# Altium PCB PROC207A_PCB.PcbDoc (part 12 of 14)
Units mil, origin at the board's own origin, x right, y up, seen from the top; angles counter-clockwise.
Board outline 4094.49 x 3724.79 mil, 8 copper layers (Top Layer, L2_GND1, L3_SIG1, L4_PWR1, L5_PWR2, L6_SIG2, L7_GND2, Bottom Layer), stack 58.1 mil thick; 584 components, 399 nets, 8440 pads, 5258 vias.
Unrouted connection lines stored in the file: 9.
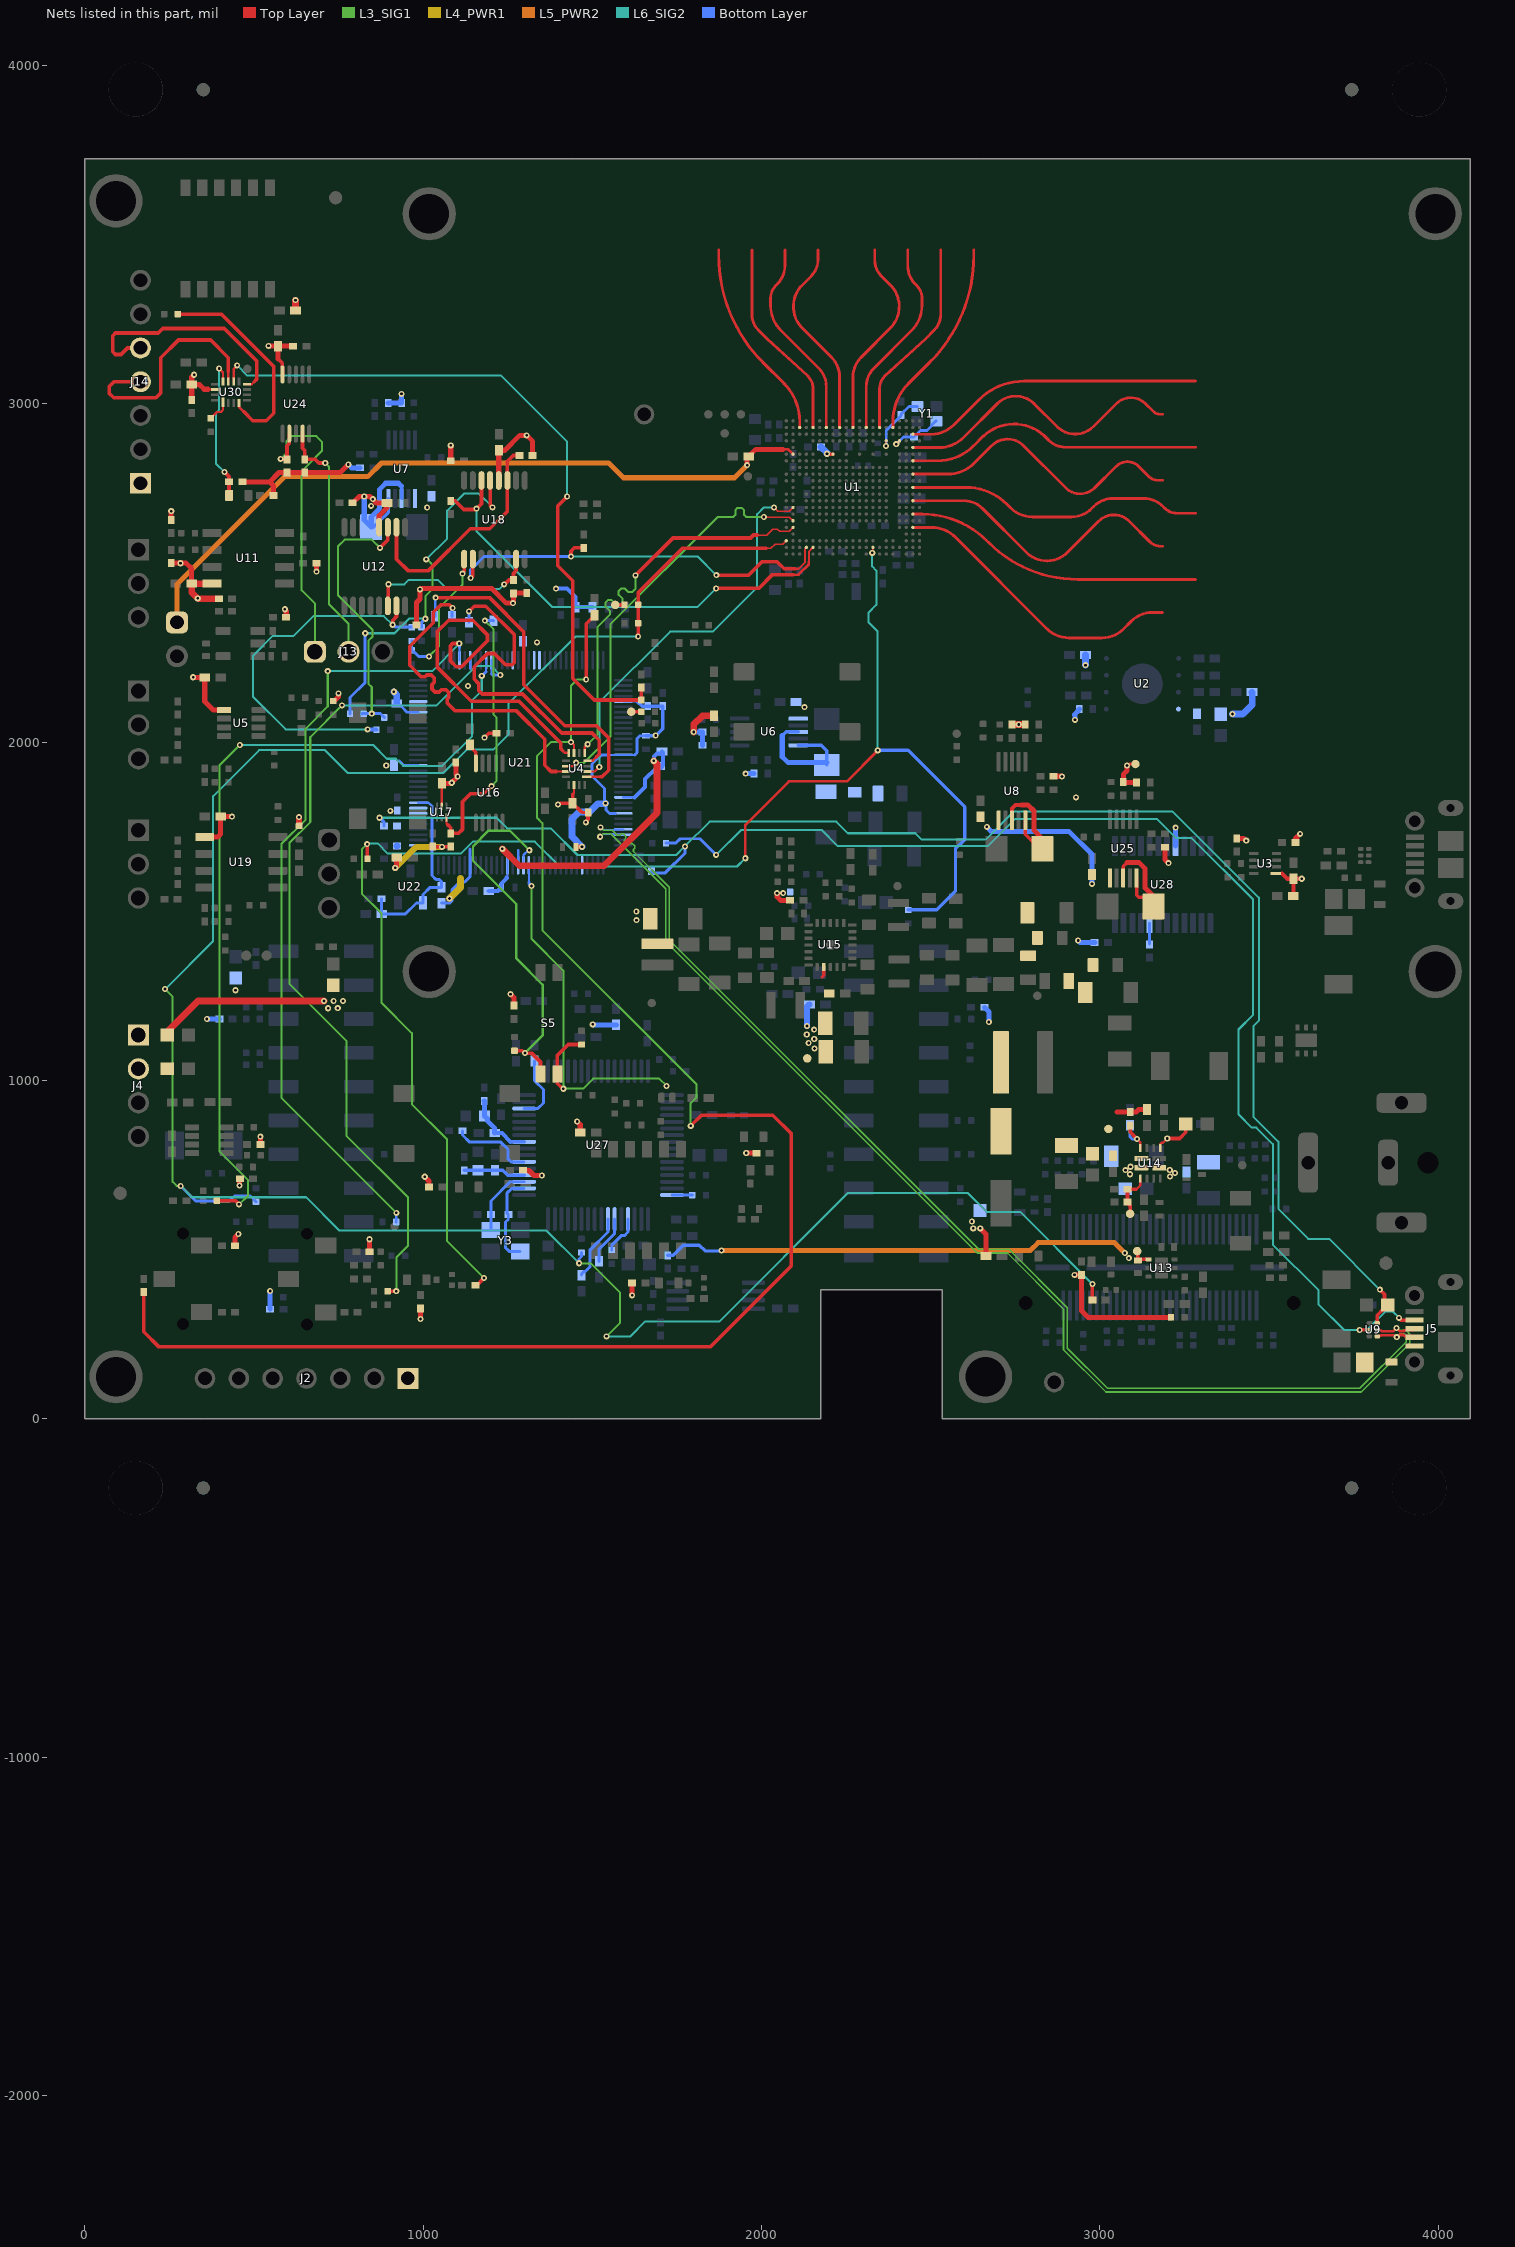
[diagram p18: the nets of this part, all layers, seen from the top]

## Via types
v1: diameter 13.77, hole 7, Top Layer to L2_GND1, tented top, 4306 vias
v2: diameter 18, hole 8, Top Layer to Bottom Layer, tented both sides, 946 vias
v3: diameter 19.68, hole 8, Top Layer to Bottom Layer, tented both sides, 6 vias

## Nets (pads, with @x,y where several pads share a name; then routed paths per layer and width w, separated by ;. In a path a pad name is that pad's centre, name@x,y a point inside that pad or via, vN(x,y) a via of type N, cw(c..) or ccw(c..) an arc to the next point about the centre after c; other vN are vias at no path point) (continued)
RADAR_USER_LED_GPIO_6: R222.1 R242.2 R263.2 R264.2 R269.2 U1.AA19 | length 7063.8
  Top Layer w4: 2014.31,2573.02 2027.72,2573.02 2040.47,2585.77 2063.47,2585.77 U1.AA19@2073.47,2595.77
  Top Layer w10.8: v2(1635.26,2312.74) R264.2@1635.26,2351.95 R269.2@1635.26,2406.15 1635.26,2442.97 1765.31,2573.02 2014.31,2573.02 ; R263.2@2977.86,351.35 2977.86,398.33 v2(2978.22,398.69)
  L3_SIG1 w6: v2(236.88,1270.33) 259.2,1248.05 259.2,700.51 271.18,688.54 v2(283.06,688.54) ; v2(1460.84,459.82) 1495.18,459.82 1582,373 1582,284 v2(1542,244)
  L6_SIG2 w6: v2(236.88,1270.33) 379.16,1412.61 379.16,1840.8 515.17,1976.8 709.66,1976.8 777.32,1909.14 1059.03,1909.14 1128.08,1978.2 1206.97,1978.2 1251.54,2022.76 1251.54,2113.54 1450.73,2312.74 v2(1635.26,2312.74) ; v2(283.06,688.54) 316.53,655.07 653.73,655.07 751.97,556.83 1363.83,556.83 v2(1460.84,459.82) ; v2(1542,244) 1612.79,244 1656.79,288 1876.04,288 2255.52,667.48 2609.94,667.48 2665.65,611.77 2765.14,611.77 v2(2978.22,398.69)
  Bottom Layer w8.7: v2(283.06,688.54) 327.1,644.49 428.14,644.49 441.99,658.35 489.12,658.35 R222.1@505.82,641.64 ; v2(1460.84,459.82) 1460.84,472.55 1467.83,479.54 R242.2@1467.83,491.55
RADAR_USER_SW_GPIO_2: R66.2 R175.1 R214.2 U1.H20 | length 4660.7
  Top Layer w4: v2(2327.26,2559.93) 2329.38,2562.05 U1.H20@2329.38,2576.08
  Top Layer w8: v2(1952.11,1657.11) 1952.11,1756.07 2080.64,1884.6 2252.16,1884.6 v2(2343.54,1975.99)
  Top Layer w10.8: R214.2@834.13,1655.53 v2(834.13,1698.84) ; R66.2@1154.24,394.98 1158.82,394.98 v2(1179.95,416.12)
  L3_SIG1 w6: v2(834.13,1698.84) 818.86,1683.58 818.86,1552.45 876.76,1494.56 876.76,1229.96 966.37,1140.35 966.37,930.45 1070.96,825.86 1070.96,525.12 v2(1179.95,416.12)
  L6_SIG2 w6: v2(834.13,1698.84) 836.42,1701.14 865.15,1701.14 895.35,1670.93 1111.38,1670.93 1146.6,1706.15 1330.25,1706.15 1403.74,1632.66 1927.66,1632.66 v2(1952.11,1657.11) ; v2(2327.26,2559.93) 2326.77,2559.45 2326.77,2520.23 2339.51,2507.49 2339.51,2405.95 2316.34,2382.78 2316.34,2354.72 2343.54,2327.51 v2(2343.54,1975.99)
  Bottom Layer w10: v2(2343.54,1975.99) 2433.17,1975.99 2600.45,1808.71 2600.45,1712.33 2573.35,1685.23 2573.35,1559.47 2518.24,1504.36 R175.1@2433.97,1504.36
RADAR_VBGAP: C6.1 U1.P6 | length 45.6
  Top Layer w10: v2(2193.39,2852.89) 2194.61,2851.67 U1.P6@2211.27,2851.67
  Bottom Layer w20: C6.1@2176.2,2873.02 2193.39,2855.83 v2(2193.39,2852.89)
REF_FTDI: R218.2 U27.6 | length 243.9
  Bottom Layer w8.7: R218.2@1116.06,851.44 1116.06,839.23 1137.51,817.77 1229.48,817.77 1250.51,796.74 1250.51,768.55 1259.21,759.84 U27.6@1298.34,759.84
REG_1V2: C20.2 C91.2 FB2.2 R193.1 U8.8 U8.10 | length 337.2
  Top Layer w11: U8.10@2779.84,1769.27 2779.84,1727.89 R193.1@2823.58,1684.15
  Top Layer w12: U8.8@2740.47,1769.27 2740.47,1804.47 2751,1815 2768.93,1815
  Top Layer w15: 2768.93,1815 2786.86,1815 2805.37,1796.49 2805.37,1739.68 2830.27,1714.78 R193.1@2830.27,1684.93
REG_1V8: C3.2 C82.2 FB1.2 R192.1 U6.8 U6.10 | length 385.1
  Bottom Layer w10: 2061.32,2019.32 2072.7,2030.71 U6.8@2108.47,2030.71 ; U6.10@2108.66,1991.15 2176.34,1991.15 2193,1974.49 R192.1@2193,1933.08
  Bottom Layer w15: 2061.32,2019.32 2061.32,1957.23 2077.83,1940.72 R192.1@2193,1940.72
REG_RF_1V2: C27.2 C103.2 FB3.2 R134.1 U25.8 U25.10 | length 351
  Top Layer w10: U25.8@3069.32,1599.03 3069.32,1632.87 3080.56,1644.11 ; U25.10@3108.69,1599.03 3108.69,1548.23 3114.55,1542.37 3136.94,1542.37 3159.12,1520.2 R134.1@3159.12,1514.68
  Top Layer w15: 3080.56,1644.11 3116.35,1644.11 3134.22,1626.24 3134.22,1569.44 3159.12,1544.54 R134.1@3159.12,1514.68
RS232_FTDI_RX: R120.1 U27.48 | length 60
  Bottom Layer w8.7: U27.48@1735.35,661.42 R120.1@1795.35,661.42
RS232_FTDI_TX: R121.1 U27.52 | length 117.2
  Bottom Layer w8.7: R121.1@1557.21,498.88 1557.21,513.45 1585.08,541.32 1594.62,541.32 1605.43,552.13 U27.52@1605.43,590.55
RST_FTDI: R237.2 U27.14 | length 198.4
  Bottom Layer w8.7: U27.14@1298.34,917.33 1338.8,917.33 1355.24,933.76 1355.24,973.27 1328.96,999.54 R237.2@1328.96,1057.6
RTC_CLK_IN: R269.1 TP9.1 | length 27.4
  Top Layer w10.8: TP9.1@1567.54,2405.99 1594.74,2405.99 R269.1@1594.9,2406.15
RX1: U1.W2 | length 597.4
  Top Layer w8.39: 1873.81,3437.36 ccw(c2317.7,3437.36) 2003.77,3123.54 ; 1873.81,3437.4 1873.81,3455.15 ; 2003.87,3123.44 2065.97,3061.34 ; 2066.02,3061.29 cw(c1953.11,2948.31) 2112.84,2948.36 ; U1.W2@2112.84,2930.41 2112.84,2948.28
RX2: U1.U2 | length 597.6
  Top Layer w8.39: 1971.45,3455.15 1971.45,3265.17 ccw(c2038.05,3265.13) 1990.93,3218.07 ; 1990.99,3218.01 2017,3192 2137.05,3082.32 cw(c2099.92,3045.5) 2152.21,3045.5 U1.U2@2152.21,2930.41
RX3: U1.R2 | length 597
  Top Layer w8.39: 2069.09,3455.15 2069.09,3408.26 cw(c1993.02,3408.26) 2046.81,3354.47 2042.21,3349.87 ccw(c2079.28,3312.81) 2026.86,3312.81 2026.86,3291.54 ccw(c2132.46,3291.54) 2057.79,3216.87 2169.65,3105.01 ; 2169.75,3104.91 cw(c2116.91,3052.15) 2191.58,3052.15 ; U1.R2@2191.58,2930.41 2191.58,3052.11
RX4: U1.N2 | length 597.1
  Top Layer w8.39: 2166.73,3455.15 2166.73,3425.44 cw(c2100.71,3425.44) 2147.33,3378.69 2116.33,3347.7 ccw(c2185.48,3288.13) 2117.64,3227.07 2206.65,3138.06 ; 2206.74,3137.97 cw(c2148.13,3079.46) 2230.95,3079.49 ; U1.N2@2230.95,2930.41 2230.95,3079.42
RX5: U1.L2 | length 597.1
  Top Layer w8.39: U1.L2@2270.32,2930.41 2270.32,3079.42 ; 2270.32,3079.49 cw(c2353.14,3079.46) 2294.53,3137.97 ; 2294.62,3138.06 2383.63,3227.07 ccw(c2315.79,3288.13) 2384.94,3347.7 2353.94,3378.69 cw(c2400.56,3425.44) 2334.54,3425.44 2334.54,3455.15
RX6: U1.J2 | length 597
  Top Layer w8.39: U1.J2@2309.69,2930.41 2309.69,3052.11 ; 2309.69,3052.15 cw(c2384.36,3052.15) 2331.52,3104.91 ; 2331.62,3105.01 2443.48,3216.87 ccw(c2368.81,3291.54) 2474.41,3291.54 2474.41,3312.81 ccw(c2421.99,3312.81) 2459.06,3349.87 2454.46,3354.47 cw(c2508.25,3408.26) 2432.18,3408.26 2432.18,3455.15
RX7: U1.G2 | length 597.6
  Top Layer w8.39: U1.G2@2349.06,2930.41 2349.06,3045.5 cw(c2401.35,3045.5) 2364.22,3082.32 2484.27,3192 2510.28,3218.01 ; 2510.34,3218.07 ccw(c2463.22,3265.13) 2529.82,3265.13 2529.82,3455.15
RX8: U1.E2 | length 597.4
  Top Layer w8.39: U1.E2@2388.43,2930.41 2388.43,2948.28 ; 2388.43,2948.36 cw(c2548.16,2948.31) 2435.25,3061.29 ; 2435.3,3061.34 2497.4,3123.44 ; 2497.5,3123.54 ccw(c2183.57,3437.36) 2627.46,3437.36 ; 2627.46,3437.4 2627.46,3455.15
SOP0_FTDI: R249.1 U27.55 | length 200.5
  Bottom Layer w8.7: R249.1@1468.31,424.73 1468.31,428.66 1475.77,436.12 1479.7,436.12 1492.39,448.81 1492.39,498.39 1546.38,552.38 U27.55@1546.38,590.55
SOP1_FTDI: R248.1 U27.54 | length 144.6
  Bottom Layer w8.7: R248.1@1519.16,465.41 1519.16,500.71 1566.06,547.61 U27.54@1566.06,590.55
SPI_MUX_ENn: R10.1 U28.20 | length 61.9
  Bottom Layer w8.7: R10.1@3147.41,1403.19 U28.20@3147.41,1465.05
SPIB_CLK: R285.2 U30.1 | length 69.6
  Top Layer w7: R285.2@371.87,2957.78 372.36,2957.78 378.21,2963.63 378.21,2964.13 390.46,2976.38 401.91,2976.38 408.24,2982.71 U30.1@408.24,3005.31
SPIB_CS0_N: J14.4 U30.11 | length 700.7
  Top Layer w7: U30.11@423.99,3066.34 423.99,3094.85
  Top Layer w10.8: J14.4@164.17,3065.75 86.01,3065.75 71.97,3051.7 71.97,3030.95 84.85,3018.06 209.81,3018.06 224.17,3032.43 224.17,3136.95 276.57,3189.36 371.67,3189.36 423.99,3137.04 423.99,3094.85
SPIB_MISO: J14.5 U30.8 | length 703.8
  Top Layer w7: U30.8@479.11,3058.46 493.33,3058.46 500.4,3065.53
  Top Layer w10.8: J14.5@164.17,3165.75 163.82,3165.39 125.78,3165.39 106.76,3146.38 90.06,3146.38 82.21,3154.23 82.21,3201.74 90.12,3209.66 216.36,3209.66 230.05,3223.35 411.61,3223.35 507.46,3127.5 507.46,3072.6 500.4,3065.53
SPIB_MOSI: R286.2 U30.4 | length 626.5
  Top Layer w7: U30.4@455.49,3003.35 455.49,2991.32 470.11,2976.69
  Top Layer w10.8: R286.2@274.53,3265.75 403.23,3265.75 558.07,3110.9 558.07,2972.72 535.9,2950.55 496.26,2950.55 470.11,2976.69
SYS_RST_OUT: D9.1 R65.2 U30.12 | length 438.3
  Top Layer w7: v2(396.6,3104.72) 408.24,3093.09 U30.12@408.24,3066.34
  Top Layer w10.8: v2(412.68,2798.7) 426.03,2785.35 R65.2@426.03,2769.64 D9.1@426.03,2729.64
  L6_SIG2 w6: v2(396.6,3104.72) 396.6,2982.52 387.21,2973.12 387.21,2824.17 v2(412.68,2798.7)
SYS_RST_OUT_SPIB_CS0_N: R146.1 R268.2 U30.10 | length 2116.5
  Top Layer w7: U30.10@439.74,3066.34 439.74,3103.81 v2(450.04,3114.12)
  Top Layer w10.8: v2(1425.36,2726.55) 1397.29,2698.47 1397.29,2521.89 1441.98,2477.2 1441.98,2188.81 1505.76,2125.04 R268.2@1644.95,2125.04 1644.95,2160.46 R146.1@1645.54,2161.05
  L6_SIG2 w6: v2(450.04,3114.12) 480.15,3084.02 1230.23,3084.02 1425.36,2888.89 v2(1425.36,2726.55)
TX1: U1.B3 | length 888.6
  Top Layer w8.39: U1.B3@2447.49,2910.73 2501.91,2910.73 ccw(c2502.08,3004.03) 2568.14,2938.14 2642.08,3012.08 cw(c2775.58,2878.79) 2775.62,3067.44 3283.26,3067.44
TX2: U1.B5 | length 888
  Top Layer w8.39: U1.B5@2447.49,2871.36 2525.95,2871.36 ccw(c2525.95,2971.36) 2596.66,2900.65 2696.89,3000.88 cw(c2751.29,2945.75) 2806.17,3000.39 ; 2806.34,3000.21 2873.54,2933.02 ccw(c2927.11,2987) 2981,2933.34 3046.18,2998.52 cw(c3091.8,2956.43) 3133.89,3002.05 3158.34,2977.6 ccw(c3177.16,2996.42) 3177.16,2969.8 3185.62,2969.8
TX3: U1.B7 | length 888.6
  Top Layer w8.39: U1.B7@2447.17,2832.19 2520.66,2832.19 ccw(c2520.75,2982.28) 2626.97,2876.24 2655.65,2904.92 cw(c2746.3,2808.18) 2843.04,2898.82 2848.98,2892.89 ccw(c2899.01,2942.92) 2899.01,2872.16 3283.26,2872.16
TX4: U1.B9 | length 888.6
  Top Layer w8.39: U1.B9@2447.49,2792.62 2551,2792.62 ccw(c2551.05,2901.87) 2628.43,2824.74 2679.29,2875.6 cw(c2727.43,2829.44) 2773.59,2877.59 2896.85,2754.33 ccw(c2942.03,2795.96) 2983.66,2750.79 3049.08,2816.2 cw(c3081.8,2782.6) 3115.03,2815.7 ; 3115.16,2815.56 3146.34,2784.38 ; 3146.39,2784.33 ccw(c3170.07,2808.02) 3170.07,2774.53 ; 3170.11,2774.53 3185.62,2774.53
TX5: U1.B11 | length 888.4
  Top Layer w8.39: U1.B11@2447.49,2753.25 2605.6,2753.25 cw(c2605.6,2583.89) 2725.4,2703.6 2735.49,2693.51 ccw(c2801.21,2759.24) 2801.21,2666.29 2916.71,2666.29 ccw(c2916.71,2749.76) 2975.74,2690.74 2982,2697 cw(c3039.85,2639.15) 3039.85,2720.96 3127.76,2720.96 cw(c3127.76,2635.62) 3188.71,2695.36 3192.11,2691.95 ccw(c3228.48,2728.32) 3228.48,2676.89 3283.26,2676.89
TX6: U1.B13 | length 888.1
  Top Layer w8.39: U1.B13@2447.49,2713.88 2599.37,2713.88 cw(c2599.34,2639.03) 2652.24,2691.98 ; 2652.31,2691.91 2784.77,2559.45 ; 2784.81,2559.41 ccw(c2790.7,2565.38) 2784.96,2559.27 ccw(c2843.79,2622.59) 2904.99,2561.55 2996.61,2653.18 ; 2996.74,2653.31 cw(c3041.99,2608.56) 3086.59,2653.97 ; 3086.62,2653.94 3147.73,2592.83 ccw(c3180.51,2625.61) 3180.51,2579.25 3185.62,2579.25
TX7: U1.B15 | length 887.8
  Top Layer w8.39: U1.B15@2447.49,2674.51 2475.12,2674.51 cw(c2475.23,2403.67) 2666.75,2595.17 ; 2666.83,2595.09 2671.77,2590.15 ccw(c2933.72,2851.99) 2933.73,2481.61 ; 2933.85,2481.61 3283.26,2481.61
TX8: U1.B17 | length 888.3
  Top Layer w8.39: U1.B17@2447.49,2635.14 2502.16,2635.14 cw(c2502.13,2533.26) 2574.19,2605.27 2844.15,2335.32 ; 2844.22,2335.24 ccw(c2908.37,2399.43) 2908.37,2308.68 ; 2908.41,2308.68 3006.7,2308.68 ; 3006.76,2308.68 ccw(c3006.76,2398.36) 3070.2,2334.97 3092.8,2357.58 cw(c3156.4,2294.15) 3156.4,2383.97 3185.62,2383.97
UARTB_RX: J13.2 R275.1 U24.4 | length 729.6
  Top Layer w10.8: U24.4@643.35,2912.24 643.35,2868.98 649.99,2862.34 R275.1@649.99,2836.81 ; R275.1@650.21,2836.59 679.9,2836.59 690.9,2825.59 v2(710.5,2825.59)
  L3_SIG1 w6: v2(710.5,2825.59) 721.39,2814.69 721.39,2407.64 779.43,2349.6 J13.2@779.43,2267.59
UARTB_TX: J13.1 R274.1 U24.2 | length 937.7
  Top Layer w10.8: v2(578.51,2837.87) 579.16,2837.23 594.55,2837.23 R274.1@597.17,2834.62 ; R274.1@597.17,2836.59 597.17,2876.67 604.01,2883.5 U24.2@604.01,2912.26
  L3_SIG1 w6: v2(578.51,2837.87) 595.34,2854.7 595.34,2889.02 611.13,2904.81 683.9,2904.81 701.46,2887.26 701.46,2862.43 640.38,2801.36 640.38,2449.39 679.43,2410.33 J13.1@679.43,2267.59
USB_5V: C86.2 J5.1 L9.1
VBAT: J4.2 R32.1
VBUS_1_DETECT: C118.2 R236.1 R239.2 U21.1 | length 2.4
  Bottom Layer w8.7: C118.2@922.79,1693.47 C118.2@924.55,1695.23
VCC_3V3: C34.1 C35.2 C36.1 C38.2 C40.1 C41.1 C52.2 C56.1 C57.1 C58.1 C59.1 C65.1 C104.1 C107.1 C109.2 C133.1 C135.1 C136.1 J2.1 J14.1 L14.2 R2.2 R5.2 R7.2 R8.2 R12.1 R14.2 R17.2 R22.2 R28.2 R44.2 R49.2 R50.1 R64.2 R65.1 R70.2 R82.2 R91.2 R94.1 R95.2 R97.2 R98.2 R99.2 R104.2 R105.2 R106.2 R107.2 R112.1 R115.1 R123.2 R127.2 R128.2 R135.2 R136.2 R138.2 R141.2 R142.1 R147.1 R149.1 R151.1 R154.2 R156.2 R157.2 R161.2 R163.2 R164.2 R165.2 R166.2 R172.2 R173.2 R200.1 R204.2 R207.2 R213.2 R253.2 R258.2 R262.2 R271.2 R274.2 R275.2 R277.2 R279.2 R283.1 R287.2 TP17.1 U2.8 U3.1 U4.14 U5.5 U6.6 U7.6 U7.8 U7.10 U8.6 U11.8 U12.12 U16.10 U17.5 U18.12 U19.5 U24.10 U25.6 U28.8 U30.14 | length 5985.8
  Top Layer w6.5: U17.5@1054.8,1809.55 1054.8,1826.78
  Top Layer w7: 362.97,3042.72 U30.14@384.62,3042.72 ; 1441.72,1845.84 1445.71,1849.83 U4.14@1445.71,1873.86
  Top Layer w8: 1054.8,1826.78 C52.2@1054.8,1878.55
  Top Layer w10: 570.67,3133.69 583.17,3121.18 583.17,3109.77 584.32,3108.62 U24.10@584.32,3087.46 ; R123.2@1028.35,1691.39 R138.2@1081.26,1691.39 ; C104.1@1137.8,1993.11 1144.61,1986.3 1144.61,1981.18 1155.59,1970.19 U16.10@1155.59,1937.85 ; v2(1181.1,2013.78) 1193.57,2026.25 R95.2@1217.06,2026.25 ; v2@1404.35,1820.02 C40.1@1441.72,1820.02 ; 1441.72,1845.84 C40.1@1441.72,1820.02 ; R5.2@1487.66,1792.41 1469.33,1792.41 C40.1@1441.72,1820.02 ; v2(3080.24,1931.12) 3082.41,1931.12 3086.94,1935.65 TP17.1@3105.44,1935.65 ; U3.1@3520.39,1611.98 3538.8,1611.98
  Top Layer w12: v2(1480.6,1763.15) 1480.6,1765.3 1487.66,1772.35 R5.2@1487.66,1792.41 ; 3538.8,1611.98 3554.27,1596.5 C36.1@3572.12,1596.5 ; C56.1@3572.22,1545.8 3572.12,1545.9 C36.1@3572.12,1596.5 ; v2(3596.96,1596.5) C36.1@3572.12,1596.5
  Top Layer w15: R97.2@254.77,2529.42 v2@282.35,2529.42 ; R98.2@254.77,2657.7 254.77,2682.89 v2(255.07,2683.18) ; v2(282.56,2529.21) v2@282.35,2529.42 ; C65.1@315.62,2468.79 315.42,2468.99 315.42,2513.32 299.32,2529.42 v2@282.35,2529.42 ; R271.2@315.66,3012.1 C136.1@315.66,3057.1 ; v2(319.74,2192.12) 319.88,2191.99 354.05,2191.99 C38.2@354.18,2191.85 354.18,2120.48 379.42,2095.24 U5.5@411.27,2095.24 ; v2(322.86,3086.49) 315.66,3079.29 C136.1@315.66,3057.1 ; U19.5@354.01,1720.14 392.47,1720.14 401.26,1728.93 C109.2@401.26,1780.14 434.36,1780.14 v2(434.5,1780) ; 362.97,3043.47 352.32,3043.47 338.69,3057.1 C136.1@315.66,3057.1 ; R204.2@443.81,512.08 443.81,536.55 v2(453.56,546.3) ; v2(457.16,689.73) 457.42,689.99 457.42,709.08 R22.2@457.67,709.34 ; R65.1@465.4,2769.64 546.41,2769.64 ; R17.2@518.5,810.73 518.5,834.19 v2(518.57,834.26) ; v2(542.61,3171.73) 542.97,3171.37 570.31,3171.37 C135.1@570.67,3171.01 ; R64.2@557.48,2729.64 557.48,2758.57 546.41,2769.64 ; 570.67,3133.69 C135.1@570.67,3171.01 ; v2(591.03,2393.29) 591.03,2392.48 595.04,2388.47 R82.2@595.04,2369.21 ; R253.2@615.67,3171.01 C135.1@570.67,3171.01 ; R161.2@684.56,2528.79 684.68,2528.66 684.68,2504.36 v2(684.8,2504.24) ; v2(778.64,2821.3) 754.55,2797.22 R275.2@650.21,2797.22 R274.2@597.17,2797.22 573.98,2797.22 546.41,2769.64 ; R7.2@791.59,2707.74 810.53,2726.68 v2(825.71,2726.68) 842.92,2726.68 851.01,2718.59 v2(851.1,2718.59) 862.11,2707.58 C41.1@892.99,2707.58 892.99,2693.18 869.69,2669.88 U12.12@869.69,2635.52 ; v2(841.23,530.81) 841.49,530.55 R207.2@841.49,494.32 ; v2(917.32,1628.63) 917.32,1629.44 921.46,1633.58 R213.2@921.46,1658.85 ; R8.2@979.95,2346.78 979.95,2413.12 990.66,2423.83 v2(990.66,2452.12) ; v2@990.09,2452.69 v2(990.66,2452.12) ; R28.2@991.94,326.81 992,326.75 992,295 v2(992.06,294.94) ; v2(1004.56,715.51) 1016.85,703.21 1016.85,687.73 1016.93,687.66 R287.2@1016.93,685.39 ; C52.2@1054.8,1878.55 1081.85,1878.55 1083.55,1880.24 v2(1084.36,1880.24) 1084.36,1880.93 1101.79,1898.36 v2(1101.79,1899.05) 1101.79,1899.86 1096.4,1905.26 R163.2@1096.4,1939.9 ; R127.2@1081.36,2832.49 1081.36,2877.7 v2(1081.41,2877.75) ; U18.12@1223.27,2773.84 1223.27,2863.03 C107.1@1223.43,2863.19 1241.5,2863.19 1285.66,2907.34 v2(1305.73,2907.34) 1323.43,2889.64 R149.1@1323.43,2847.79 ; v2(1257.75,1255.36) 1268.16,1244.95 R164.2@1268.16,1221.22 ; v2(1265.58,2411.26) 1245.7,2411.26 1202.51,2454.45 993.8,2454.45 991.47,2452.12 v2(990.66,2452.12) ; v2@1266.79,2413.33 1266.79,2440.45 1267.35,2441.03 R128.2@1306.31,2441.03 ; R165.2@1295.39,734.37 1312.74,734.37 1327.59,719.53 v2(1350.76,719.53) ; v2(1454.94,878.85) 1464.27,869.51 R70.2@1464.27,846.87 ; v2@1617.56,365.21 R141.2@1617.54,401.58 ; v2(1954.92,785.85) 1969.75,785.85 1970.37,785.23 R172.2@1984.68,785.23 ; v2@2046,1548.91 2046.58,1548.34 2046.58,1543 2057.17,1532.41 2070.84,1532.41 2071.18,1532.75 L14.2@2084.25,1532.75 ; R106.2@2863.48,1899.92 2863.89,1899.51 2887.71,1899.51 v2(2888.12,1899.1) ; v2(2925.33,425.58) 2925.61,425.31 2945.79,425.31 R258.2@2946.06,425.04 2946.06,319.4 2965.66,299.8 R91.2@3210.68,299.8 ; v2@3080.43,1930.94 3080.43,1916.01 3069.53,1905.11 R142.1@3069.53,1881.83 3069.32,1881.62 R136.2@3108.69,1881.62 ; R135.2@3192.33,1689.68 3192.33,1653.59 v2(3203.12,1642.79) ; R151.1@3404.89,1715.99 3425.32,1715.99 3432.1,1709.22 v2(3432.91,1709.22) ; R283.1@3578.52,1703.48 3578.52,1715.61 v2(3592.28,1729.36)
  Top Layer w20: U11.8@375.62,2468.79 C65.1@315.62,2468.79 315.62,2443.36 v2(333.48,2425.5) 334.74,2424.24 R157.2@395.99,2424.24 ; R277.2@622.24,3276 622.24,3306.43 v2(622.67,3306.85) ; v2(1799.35,2030.31) 1799.35,2052.32 1825.13,2078.09 R262.2@1859.79,2078.09 ; R115.1@2740.47,2051.87 2740.86,2052.26 v2(2760.3,2052.26) 2779.45,2052.26 R107.2@2779.84,2051.87
  L4_PWR1 w18: v2(917.32,1628.63) 979.62,1690.93 v2(1055.39,1690.93)
  Bottom Layer w10: R200.1@852.95,2635.41 868.81,2651.26 896.69,2679.15 U7.10@896.69,2720.53 ; 935.32,2757.08 936.14,2756.26 936.14,2720.61 U7.8@936.06,2720.53
  Bottom Layer w15: v2(360.45,1181.74) 360.7,1182 R156.2@397.32,1182 ; v2(445.16,1267.07) v2@445.42,1267.33 ; R166.2@546.9,324.37 547.44,324.92 v2(547.44,377.74) ; v2(778.64,2821.3) 788.76,2811.18 R104.2@813.05,2811.18 ; v2(825.71,2726.68) 825.71,2656.74 R200.1@846.26,2636.19 846.26,2666.04 871.16,2690.94 871.16,2747.75 889.03,2765.61 926.79,2765.61 935.32,2757.08 ; R105.2@896.69,3003.13 R112.1@936.06,3003.13 935.85,3003.34 v2(935.85,3029.84) ; v2(1501,1166.04) 1501.81,1166.04 1503.1,1164.75 1566.21,1164.75 R99.2@1570.53,1164.74 ; v2(1799.35,2030.31) 1825.85,2030.31 R94.1@1826.06,2030.52 R14.2@1826.06,1991.15 ; v2(1953,1907.25) 1953.13,1907.38 1977.88,1907.38 R2.2@1978.01,1907.51 ; R173.2@2659.23,1216.29 2672.41,1203.11 2672.41,1173.77 v2(2671.98,1173.35) ; v2(2666.04,1749.94) 2680.14,1735.84 2909.49,1735.84 2976.65,1668.68 v2(2976.65,1581.54) ; v2(2926.85,2066.35) 2926.85,2079.6 2926.05,2080.4 2926.05,2082.53 2937.21,2093.69 2937.21,2095.66 R50.1@2939.55,2098 ; v2(2936.03,1413.76) 2936.48,1413.76 2942.09,1408.15 R12.1@2985.05,1408.15 ; U28.8@3224.16,1693.42 v2(3224.16,1747.66)
  Bottom Layer w20: R44.2@2957.73,2257.96 2957.73,2228.12 v2(2957.79,2228.06) ; v2(3392.12,2083.37) 3422.87,2083.37 3450.91,2111.41 3450.91,2146.19 3450.12,2146.98 R49.2@3450.12,2148
  other v2: 1617.58,365.19 2046,1553.91 2064,1553.91 1398.42,1816.25 2929.38,1837.11 2126.86,2103.85 1011.63,2694.18 846.05,2698.8
VCC_12V: C30.1 C49.1 C54.1 C60.1 L1.2 R4.2 R9.1 TP7.1 U14.7 | length 92
  Top Layer w15: 3050.72,907.07 3107.58,907.07 3115.06,914.54 R4.2@3139.58,914.54
VCC_CAN_3V3: C72.2 L4.2 R129.2 R266.1 | length 56.6
  Top Layer w15: R266.1@734.45,2121.53 736.79,2123.87 739.22,2123.87 748.93,2133.58 748.93,2144.17 v2(749.51,2144.74)
  Top Layer w18: R129.2@632.96,1752.79 v2(632.96,1778.51)
  other v2: 1630.72,1474.29 1630.05,1499.73
VCC_XDS_3V3: C105.1 C106.2 C108.1 C113.2 C114.1 C115.1 C116.2 L7.1 R195.2 R196.2 R202.1 R231.2 R233.2 TP20.1 U13.1 U21.7 U21.8 U21.16 U21.26 U21.28 U21.39 U21.47 U21.51 U21.52 U21.69 U21.79 U21.90 U21.101 U21.113 U21.122 | length 2994.6
  Top Layer w10: C105.1@3112.29,468.03 3115.6,471.33 U13.1@3144.27,471.33
  Top Layer w10.8: TP20.1@3110.45,495.88 3112.29,494.03 C105.1@3112.29,468.03
  Top Layer w12: C108.1@1451.68,1690.92 1451.82,1691.06 1469.28,1691.06 v2(1469.42,1691.2)
  L5_PWR2 w15: v2(1881.42,497.35) 2794.45,497.35 2817.87,520.78 3043.72,520.78 v2(3074.14,490.36)
  L4_PWR1 w20: v2(1077.76,1538.38) 1109.9,1570.52 1109.9,1597.29
  Bottom Layer w6: 1542.21,1962.84 U21.79@1591.56,1962.84 ; U21.79@1591.66,1962.94 1625.68,1962.94 ; U21.69@1591.66,2120.42 1633.4,2120.36
  Bottom Layer w7: 952.17,2088.93 U21.26@985.36,2088.93 ; U21.39@1138.9,2219.16 U21.39@1138.9,2242.47
  Bottom Layer w8: 929.33,1945.19 943.07,1931.45 U21.16@985.36,1931.45 ; U21.113@1280.63,1636.17 1280.63,1680.3
  Bottom Layer w8.7: C106.2@937.12,2103.97 952.17,2088.93 ; U21.122@1138.9,1636.17 1138.9,1684.26 ; v2@1536.24,1819.4 1536.24,1863.41 1499.11,1900.54 1499.11,1935.72 1526.23,1962.84 1542.21,1962.84 ; v2(1538.71,1819.4) 1540,1818.11 1540,1800.42 1550.65,1789.78 U21.90@1568.45,1789.78 ; 1625.68,1962.94 1632.04,1969.3 1632.04,2010.7 1640.58,2019.25 C114.1@1658,2019.25
  Bottom Layer w9: R233.2@1054.62,1524.36 1077.65,1524.36 1085.43,1532.14 1085.43,1563.79 1108.32,1586.68 1122.43,1586.68 1138.9,1603.16 U21.122@1138.9,1636.17
  Bottom Layer w10: 1633.4,2120.36 1646.78,2106.97 R231.2@1663.56,2106.97 1708.2,2106.96 1708.21,2039.85 1687.61,2019.25 C114.1@1658,2019.25 ; L7.1@1722.98,483.43 1738.83,483.43 1768.93,513.52 1815.95,513.52 1833.21,496.27 1880.34,496.27 v2(1881.42,497.35)
  Bottom Layer w12: v2(1392.63,2454.02) 1425.34,2454.02 1449.62,2429.74 R196.2@1449.62,2399.25 R195.2@1500.19,2399.25
  Bottom Layer w20: v2(913.04,2149.22) 921.53,2140.74 C106.2@921.53,2114.19 ; v2(1469.42,1691.2) 1439.63,1720.98 1439.63,1773.25 1459.91,1793.53 1491.7,1793.53 1516.68,1818.51 1537.81,1818.51 v2(1538.71,1819.4)
  other v2: 3085.92,475 902.68,1797.2 890.8,1931.15 1687.06,2019.8 1132.59,2166.31 1336.03,2295.45
VDDC_1: C124.1 C125.2 C126.2 C127.1 U21.87 U21.115 | length 1128.1
  Top Layer w20: v2(1233.78,1685.06) 1283.8,1635.04 1534.58,1635.04 1690.85,1791.31 1690.85,1935.48 v2(1681.38,1944.95)
  Bottom Layer w7: v2(1233.78,1685.06) 1249.14,1669.7 U21.115@1249.14,1636.17 ; 1245.8,1599.6 1249.14,1602.94 U21.115@1249.14,1636.11 ; U21.87@1591.66,1836.96 1625.07,1836.96
  Bottom Layer w12: C126.2@1193.75,1560.97 1221.46,1560.97 1224.8,1564.32 1229.3,1564.32 1230.8,1565.82 1230.8,1583 1247,1599.19 ; 1625.07,1836.96 1655.98,1867.87 1655.98,1891.07 1689.13,1924.22 1703.06,1924.22 1705.92,1927.08 C124.1@1705.92,1929.29 1708.7,1932.07 1708.7,1969.34 C125.2@1705.63,1972.41 1699.82,1966.6 1690.84,1966.6 1682.53,1958.28 1682.53,1946.1 v2(1681.38,1944.95)
VIN1_PR1: R9.2 R23.2 U14.6 | length 136.9
  Top Layer w7: v2(3110.02,827.42) 3119.67,817.77 U14.6@3119.67,800.34
  Top Layer w10.8: R9.2@3089.8,867.7 3089.8,847.64 v2(3110.02,827.42)
  Bottom Layer w8.7: R23.2@3089.8,867.7 3089.8,833.13 3095.51,827.42 v2(3110.02,827.42)
VIN2_CP2: R36.1 R75.2 U14.3 | length 213.1
  Top Layer w7: U14.3@3178.72,800.34 3178.72,812.26 3182.82,816.36 3186.87,816.36 v2(3199.3,828.79)
  Top Layer w10.8: v2(3199.3,828.79) 3236.25,828.79 3254.24,846.78 R36.1@3254.24,871.48
  Bottom Layer w8.7: v2(3199.3,828.79) 3236.25,828.79 3253.56,846.1 R75.2@3253.56,871.32
VOUT_STATUS: R27.2 R73.1 TP13.1 U14.9 | length 138.3
  Top Layer w7: 3108.09,678.47 3119.67,690.05 U14.9@3119.67,709.79
  Top Layer w10.8: R27.2@3082.15,641.13 R27.2@3081.81,641.47 ; TP13.1@3089.63,606.28 3089.63,629.42 3081.81,637.24 R27.2@3081.81,641.47 ; 3108.09,678.47 R73.1@3081.81,678.47 R27.2@3081.81,641.47
VPHY_FTDI: C141.1 C142.2 L2.2 U27.4 | length 182.4
  Bottom Layer w10: L2.2@1121.74,734.43 C141.1@1161.74,734.43 1235.28,734.43 1249.21,720.49 U27.4@1298.34,720.47
VPLL_FTDI: C145.1 C146.2 L3.2 U27.9 | length 206.3
  Bottom Layer w10: 1258.41,818.9 U27.9@1298.34,818.9
  Bottom Layer w12: C146.2@1211.05,845.03 1232.28,845.03 1258.41,818.9
  Bottom Layer w15: L3.2@1180.46,939.99 1180.8,939.65 C145.1@1180.8,894.69 ; C145.1@1181.13,895.34 1189.38,887.09 1189.38,881.01 1211.05,859.34 C146.2@1211.05,845.03
VPP_1P7: C31.1 P1.1 U1.Y6 | length 2153
  Top Layer w8: 2063.98,2865.87 2078.96,2865.87 U1.Y6@2093.15,2851.67
  Top Layer w15: v2(1957.43,2819.04) 1957.43,2840.01 C31.1@1962.1,2844.69 1983.29,2865.87 2063.52,2865.87
  L5_PWR2 w15: P1.1@272.13,2354.41 272.13,2467.34 589.85,2785.05 835.8,2785.05 876.51,2825.75 1548.25,2825.75 1592,2782 1920.39,2782 v2(1957.43,2819.04)
VSYS_IN: C50.1 C61.1 C62.1 C64.1 C74.1 C137.1 C154.2 J4.1 R30.1 R31.1 R145.2 R155.2 R174.1 TP15.1 U14.1 U14.8 U15.9 | length 698.8
  Top Layer w9: 2178.56,1305.44 2183.97,1310.85 U15.9@2183.97,1335.81
  Top Layer w15: R31.1@243.07,1134.5 R31.1@243.07,1143.46 ; v2(2646.67,562.97) 2663.76,545.88 R174.1@2663.76,481
  Top Layer w20: R31.1@243.07,1143.46 334.58,1234.97 v2(706.6,1234.97)
  Bottom Layer w18: v2(2134.6,1161.41) 2134.6,1218.04 R145.2@2141.77,1225.21
  other v2: 2625.89,563.1 2621.73,583.51 3207.43,716.31 3089.43,723.06 3222.55,726.73 3075.96,735 3206.77,735.72 3090.87,745.09 2156.68,1094.9 2139.37,1110.73 2155.87,1122.9 2133.76,1136.17 2155.76,1150.54 718.98,1213.79 747.31,1214.03 735.17,1235.21 762.8,1235.32
WU_REQ_IN: R267.2 TP8.1 | length 30
  Top Layer w10.8: TP8.1@1614.95,2090.04 R267.2@1644.95,2090.04
XDS_DCA_LP_FTDI_UARTA_RX: R147.2 U12.6 U18.7 | length 524.6
  Top Layer w10.8: U12.6@895.28,2403.24 896.43,2404.38 896.43,2465.9 v2(897.57,2467.05) ; v2@1240.14,2466.71 1253.26,2479.83 R147.2@1266.78,2479.83 1266.78,2499.12 1274.45,2506.79 U18.7@1274.45,2541.56
  L6_SIG2 w6: v2@898.05,2467.05 944.36,2467.05 957.32,2480 1043.42,2480 1070.12,2453.3 1225.81,2453.3 v2@1239.05,2466.54
  other v2: 1239.21,2466.71
XDS_DCA_LP_FTDI_UARTA_TX: R149.2 U12.10 U18.11 | length 698.9
  Top Layer w10.8: U12.10@920.87,2635.52 920.87,2541.21 954.66,2507.42 1015.41,2507.42 1138.96,2630.98 1196.75,2630.98 1248.86,2683.09 U18.11@1248.86,2773.84 1248.86,2830.63 1266.02,2847.79 R149.2@1284.06,2847.79
XDS_DCA_TCK: U1.Y14 U4.2 | length 1178.9
  Top Layer w4: v2(2037,2694) 2047.73,2683.27 2082.23,2683.27 U1.Y14@2093.15,2694.19
  Top Layer w7: U4.2@1485.24,1913.39 1506.97,1913.39 v2(1520.46,1926.88)
  L6_SIG2 w6: v2(1520.46,1926.88) 1520.46,2117.8 1729.8,2327.14 1856.24,2327.14 1987.1,2458 1987.1,2674.46 2006.64,2694 v2(2037,2694)
XDS_DCA_TDI: U1.Y17 U4.5 | length 1213.6
  Top Layer w4: 1987.1,2612.56 2015.48,2612.56 2033.15,2630.23 2046.95,2630.23 2053.31,2623.87 2081.89,2623.87 U1.Y17@2093.15,2635.14
  Top Layer w7: U4.5@1477.36,1968.51 1477.36,1986.61 1484.99,1994.24 v2(1486.12,1994.24)
  Top Layer w10.8: v2(1627.79,2493.44) 1738.37,2604.02 1967.6,2604.02 1976.13,2612.56 1987.1,2612.56
  L3_SIG1 w6: v2(1486.12,1994.24) 1515.48,2023.6 1515.48,2341.23 1549.54,2375.29 1551.66,2377.42 1551.66,2388.45 1538.63,2401.48 1538.63,2412.51 1545.98,2419.86 1557.01,2419.86 1571.07,2405.81 1582.1,2405.81 1589.46,2413.16 1589.46,2424.19 1577.57,2436.08 1577.57,2447.11 1584.92,2454.46 1595.95,2454.46 1606.82,2443.6 1617.85,2443.6 1624.24,2449.99 1627.79,2453.54 v2(1627.79,2493.44)
XDS_DCA_TDO_SOP0: R93.1 R203.1 U4.7 | length 4739.1
  Top Layer w7: v2(1436.74,2000.32) 1438.29,2000.32 1445.87,1992.74 U4.7@1445.87,1968.51
  Top Layer w10.8: R203.1@174.2,374.28 174.2,257.13 218.69,212.64 1848.22,212.64 2087.62,452.04 2087.62,843.3 2033.28,897.64 1822.38,897.64 v2(1790.77,866.02) ; v2(1481.78,2185.74) 1481.78,2350.01 R93.1@1506.76,2374.99
  L3_SIG1 w6: v2@1436.12,2000.93 1378.16,2000.93 1336.85,1959.63 1336.85,1776.03 1352.11,1760.77 1352.11,1444.89 1807.29,989.71 1807.29,949.87 1790.77,933.36 v2(1790.77,866.02) ; v2(1436.74,2000.32) 1436.74,2166.9 1455.58,2185.74 v2(1481.78,2185.74)
XDS_DCA_TMS: U1.Y16 U4.10 | length 1206.4
  Top Layer w4: v2@2014,2666 2014.26,2665.74 2082.23,2665.74 U1.Y16@2093.15,2654.82
  Top Layer w7: U4.10@1422.24,1929.13 1441.93,1929.13 v2(1452.18,1939.38)
  L3_SIG1 w6: v2(1452.18,1939.38) 1452.31,1939.25 1475.29,1939.25 1554.24,2018.19 1554.24,2350.06 1870.18,2666 1915.99,2666 1922.49,2672.5 1922.49,2686.16 1928.99,2692.66 1941.99,2692.66 1948.49,2686.16 1948.49,2672.5 1954.99,2666 v2(2006.99,2666)
XDS_FTDI_DCA_RS232_RX: R255.1 U1.V20 U18.2 | length 1246.5
  Top Layer w6: 2099.41,2512.93 2109.64,2512.93 2128.92,2532.21 2128.92,2571.44 2132.52,2575.04 U1.V20@2132.52,2576.08
  Top Layer w10.8: v2(1140.25,2485.3) 1146.5,2491.55 U18.2@1146.5,2541.56 ; v2(1436.82,2549.19) 1436.82,2564.82 1446.74,2574.74 R255.1@1474.36,2574.74 ; v2(1866.41,2494.1) 1961.66,2494.1 2000.7,2533.13 2046.64,2533.13 2066.85,2512.93 2099.41,2512.93
  L6_SIG2 w6: v2(1436.82,2549.19) 1811.32,2549.19 v2(1866.41,2494.1)
  Bottom Layer w8.7: v2(1140.25,2485.3) 1140.25,2510.05 1179.39,2549.19 v2(1436.82,2549.19)
XDS_FTDI_DCA_RS232_TX: R256.1 U1.U20 U18.14 | length 1426.8
  Top Layer w6: 2139.9,2533.46 2139.9,2563.77 U1.U20@2152.21,2576.08
  Top Layer w8: 2093.74,2495.6 2109.29,2495.6 2139.92,2526.24 2139.92,2533.46
  Top Layer w10.8: R256.1@1081.26,2713.87 1094.02,2713.87 1119.66,2688.23 1153.29,2688.23 1155.65,2690.59 v2(1157.6,2690.59) 1172.09,2705.08 U18.14@1172.09,2773.84 ; v2(1865.82,2454.81) 1991.48,2454.81 2032.27,2495.6 2093.74,2495.6
  L6_SIG2 w6: v2(1157.6,2690.59) 1157.6,2623.91 1382.26,2399.25 1810.26,2399.25 v2(1865.82,2454.81)
XDS_NRST: R126.2 R138.1 U17.3 | length 815
  Top Layer w6.5: U17.3@1068.58,1778.05 1068.58,1759.59 1072.95,1755.22
  Top Layer w10.8: 1072.95,1755.22 1081.26,1746.91 R138.1@1081.26,1730.76 1104.36,1730.76 1115.98,1742.38 1115.98,1823.81 1139.7,1847.54 1179.03,1847.54 v2(1201.74,1870.25)
  L3_SIG1 w6: v2(1182.07,2359.47) 1208.06,2333.48 1208.06,2081.89 1217.12,2072.83 1217.12,1885.63 v2(1201.74,1870.25)
  Bottom Layer w8.7: v2(1182.07,2359.47) 1207.59,2359.47 R126.2@1208.2,2358.86
XDS_RS232_RX: R24.2 R188.1 U18.1 | length 417.3
  Top Layer w10.8: v2(1115.84,2498.57) 1115.84,2500.52 1120.91,2505.59 U18.1@1120.91,2541.56
  L3_SIG1 w6: v2(1016.83,2253.53) 1045.95,2282.65 1045.95,2395.6 1115.84,2465.49 v2(1115.84,2498.57)
  Bottom Layer w8.7: R24.2@966.13,2299.53 R188.1@966.13,2271.53 971.13,2266.53 973.79,2266.53 986.79,2253.53 v2(1016.83,2253.53)
XDS_RS232_TX: R26.2 R181.1 U18.13 | length 1099.5
  Top Layer w10.8: U18.13@1197.68,2773.84 1197.68,2701.4 v2@1204.77,2694.31
  L3_SIG1 w6: v2(1006.41,2365.25) 1007.24,2366.08 1007.24,2432.87 1027,2452.63 1027,2525.51 1011.88,2540.63 v2(1009.05,2540.63)
  L6_SIG2 w6: v2(828.66,2322.23) 915.02,2322.23 958.04,2365.25 v2(1006.41,2365.25) ; v2(1009.05,2540.63) 1070.49,2602.07 1070.49,2684.38 1121.6,2735.48 1163.93,2735.48 v2(1204.94,2694.48)
  Bottom Layer w8.7: R26.2@783.54,2083.94 783.54,2132.01 828.51,2176.98 v2@828.51,2322.07 ; R181.1@994.75,2340.16 995.68,2341.08 995.68,2354.52 v2(1006.41,2365.25)
XDS_SCL: R199.2 S5.3 U21.112 | length 1107.8
  Top Layer w10.8: R199.2@1269.99,1088.28 1292.88,1088.28 1300,1081.16 v2(1300.84,1081.16) 1320.2,1081.16 1346.54,1054.82 S5.3@1346.54,1019.13
  L3_SIG1 w7: v2(1300.84,1081.16) 1353,1133.32 1353,1283 1275.26,1360.74 1275.26,1521.3 1146.98,1649.58 1146.98,1692.34 1193.36,1738.72 1255.67,1738.72 v2(1313.72,1680.67)
  Bottom Layer w7: U21.112@1296.38,1636.17 1296.38,1666.55 1310.5,1680.67 v2(1313.72,1680.67)
XDS_SDA: R197.2 S5.4 U21.111 | length 1220.7
  Top Layer w10.8: v2(1414.3,975.85) 1412.92,977.23 1410.78,977.23 1396.39,991.63 1396.39,1018.97 S5.4@1396.54,1019.13 1396.54,1073.91 1429.06,1106.43 R197.2@1467.94,1106.43
  L3_SIG1 w6: v2(1320.11,1575.09) 1320.11,1418.78 1414.3,1324.59 v2(1414.3,975.85) 1472.51,975.85 1502.57,1005.91 1697.53,1005.91 v2(1719.3,984.14)
  Bottom Layer w6: 1312.19,1586.11 U21.111@1312.19,1636.17
  Bottom Layer w8.7: 1312.19,1586.11 1312.19,1583.44 1320.11,1575.52 v2(1320.11,1575.09)
XDS_SOP0: R43.1 U21.42 | length 2490
  Top Layer w10.8: R43.1@390.05,644.49 445.13,644.49 v2(455.44,634.18)
  L3_SIG1 w6: v2(455.44,634.18) 456.54,634.18 482.64,660.28 482.64,705.46 397.36,790.74 397.36,1931.39 v2(457.87,1991.89)
  L6_SIG2 w6: v2(457.87,1991.89) 852.05,1991.89 892.64,1951.29 919.16,1951.29 940.34,1930.12 1056.52,1930.12 1144.41,2018.01 1144.41,2124.25 1172.99,2152.82 v2(1172.99,2196.35)
  Bottom Layer w6: 1186.15,2209.57 U21.42@1186.15,2242.47
  Bottom Layer w8.7: v2(1172.99,2196.35) 1172.99,2196.41 1186.15,2209.57
XDS_SOP1: R67.1 U21.43 | length 2577.3
  Top Layer w10.8: R67.1@894.9,377.37 920.14,377.37 v2(920.36,377.59)
  L3_SIG1 w6: v2(760,2109.05) 666,2015.05 666,1764.06 604.13,1702.19 604.13,1285.87 773.41,1116.59 773.41,835.94 954.92,654.43 954.92,511.48 920.36,476.92 v2(920.36,377.59)
  L6_SIG2 w6: v2(760,2109.05) 1039.89,2109.05 1156.7,2225.86 1200.81,2225.86 v2(1228.06,2198.6)
  Bottom Layer w6: 1201.89,2201.81 1201.89,2202.62 1202.2,2202.92 1202.2,2242.17 U21.43@1201.89,2242.47
  Bottom Layer w8.7: 1201.89,2201.81 1205.1,2198.6 v2(1228.06,2198.6)
XDS_TCK: R122.2 U4.1 | length 999.4
  Top Layer w7: U4.1@1483.27,1897.64 1523.35,1897.64 1523.43,1897.73
  Top Layer w10.8: v2(1036.81,2427.51) 1040.01,2427.51 1040.14,2427.64 1195.8,2427.64 1297.51,2325.93 1297.51,2169.81 1418.54,2048.78 1512.22,2048.78 1528.36,2032.65 1548.41,2012.59 1548.41,1917.38 1528.76,1897.73 1523.43,1897.73
  Bottom Layer w8.7: R122.2@1035.35,2372.28 1035.57,2372.49 1035.57,2426.27 v2(1036.81,2427.51)
XDS_TDI: R125.2 U4.4 | length 1018.1
  Top Layer w7: U4.4@1485.24,1944.88 1500.31,1944.88 1511.57,1956.15
  Top Layer w10.8: v2(1135.15,2386.97) 1150.57,2402.39 1184.67,2402.39 1268.7,2318.36 1268.7,2234.87 1262.91,2229.08 1243.49,2229.08 1210,2262.58 1190.05,2262.58 1150.59,2223.12 1150.59,2187.07 1163.71,2173.95 1163.71,2153.52 1174.58,2142.65 1293.66,2142.65 1409.13,2027.18 1499,2027.18 1520.38,2005.8 1520.38,1964.96 1511.57,1956.15
  Bottom Layer w8.7: v2(1135.15,2386.97) 1135.23,2386.89 1135.23,2355.12 R125.2@1135.31,2355.04
XDS_TDO: R232.2 U4.8 U21.37 | length 3326.8
  Top Layer w7: 1412.54,1975.17 1419.2,1968.51 U4.8@1430.12,1968.51
  Top Layer w10.8: v2(1106.5,2291.88) 1086.83,2291.88 1080.5,2285.55 1080.5,2240.35 1097.28,2223.58 1113.06,2223.58 1189.93,2300.44 1189.93,2317.09 1146.01,2361.01 1075.08,2361.01 1041.96,2327.88 1041.96,2221.17 1142.07,2121.05 1282.95,2121.05 1406.99,1997.02 1406.99,1980.72 1412.54,1975.17
  L3_SIG1 w6: v2(717.8,2210.27) 717.8,2105.9 652.31,2040.41 652.31,1770.71 580.82,1699.22 580.82,948.66 v2(920.63,608.84)
  L6_SIG2 w6: v2(717.8,2210.27) 1026.12,2210.27 1106.5,2290.65 v2(1106.5,2291.88)
  Bottom Layer w6: U21.37@1107.41,2242.47 1107.41,2278.43 1107.51,2278.53
  Bottom Layer w8.7: R232.2@919.84,582 920.24,582.39 920.24,608.45 v2(920.63,608.84) ; v2(1106.5,2291.88) 1107.51,2290.87 1107.51,2278.53
XDS_TMS: R124.2 U4.11 | length 980.8
  Top Layer w7: 1393.61,1913.39 U4.11@1422.24,1913.39
  Top Layer w10.8: v2(1086.89,2397.03) 1077.43,2406.49 1052.27,2406.49 1029.76,2383.97 1029.76,2353.46 959.77,2283.47 959.77,2227.33 992.93,2194.17 1005.99,2194.17 1010.6,2198.78 1023.67,2198.78 1032.38,2190.07 1032.38,2177 1025.84,2170.46 1025.84,2157.39 1034.55,2148.68 1047.62,2148.68 1054.16,2155.22 1067.23,2155.22 1075.94,2146.51 1075.94,2133.44 1071.33,2128.83 1071.33,2115.77 1093.43,2093.66 1274.14,2093.66 1358.99,2008.81 1358.99,1932.42 1378.02,1913.39 1393.61,1913.39
  Bottom Layer w8.7: R124.2@1085.33,2372.28 1085.39,2372.33 1085.39,2388.72 1085.44,2388.77 1085.44,2395.58 v2(1086.89,2397.03)
XDS_UARTA_RX: R24.1 R290.1 U12.7 | length 1119.5
  Top Layer w10.8: v2(909.53,2347.27) 909.53,2360.24 920.87,2371.58 U12.7@920.87,2403.24
  L6_SIG2 w6: v2(835.85,2038.1) 593.58,2038.1 496.74,2134.95 496.74,2256.36 553.89,2313.51 615.39,2313.51 674.97,2373.09 883.7,2373.09 v2(909.53,2347.27)
  Bottom Layer w8.7: v2(909.53,2347.27) 911.9,2347.27 918.84,2340.32 R24.1@966.57,2340.32
  Bottom Layer w10.8: v2(835.85,2038.1) 836.4,2037.55 861.27,2037.55 R290.1@861.82,2037
XDS_UARTA_TX: R26.1 R190.1 U12.11 | length 829.7
  Top Layer w10.8: v2(872.21,2574.85) 895.28,2597.92 U12.11@895.28,2635.52
  L3_SIG1 w6: v2(847.81,2084.68) 847.81,2163.31 837.8,2173.33 837.8,2300.22 850.02,2312.44 850.02,2332.38 748.49,2433.92 748.49,2580.19 767.49,2599.2 847.87,2599.2 v2(872.21,2574.85)
  Bottom Layer w8.7: R26.1@818.89,2083.94 819.63,2084.68 v2(847.81,2084.68) 873.51,2084.68 879.51,2078.67 880,2078.67 R190.1@885,2073.67
XDS_VREFA: C99.2 C102.2 R233.1 U21.9 U22.1 | length 571.2
  Bottom Layer w7: U21.9@985.36,1821.21 1015.42,1821.21 1021.58,1815.05 1021.99,1815.05 1026.09,1810.95
  Bottom Layer w8.7: C102.2@876.99,1537.45 C99.2@876.99,1492.45 947.11,1492.45 979.9,1525.23 U22.1@999.51,1525.23 999.51,1550 1020.6,1571.09 R233.1@1054.11,1571.09 1053.44,1571.77 1053.44,1588.61 1048.34,1593.71 1038.79,1593.71 1026.09,1606.41 1026.09,1810.95
XDSET_1_DM: J5.2 U9.4 U21.93 | length 3569.8
  Top Layer w7.5: U9.4@3820.35,243.53 3822.37,245.56 3830.06,245.56 3832.13,247.62 3868.94,247.62 3875.01,241.55 v2(3877.85,241.55) 3880.7,241.55 3886.95,247.8 3898.42,247.8 3901.34,244.88 3926.11,244.88 J5.2@3930.23,240.76
  L3_SIG1 w5: v2(1523.78,1748.39) 1524.87,1748.39 1533.21,1740.05 1558.52,1740.05 1573.61,1724.95 1580.47,1724.95 1584.92,1729.41 1591.78,1729.41 1598.64,1722.55 1598.64,1715.69 1594.19,1711.24 1594.19,1704.38 1601.05,1697.52 1607.9,1697.52 1611.26,1700.87 1618.12,1700.87 1624.98,1694.01 1624.98,1687.16 1621.62,1683.8 1621.62,1676.94 1727.46,1571.1 1727.46,1415.5 2641.82,501.14 2731.49,501.14 2903.77,328.86 2903.77,208.89 3022.66,90 3768.75,90 3905.8,227.04 3905.8,246.02 3901.17,250.65 3886.95,250.65 v2(3877.85,241.55)
  Bottom Layer w6: v2(1523.78,1748.39) 1525.01,1748.39 1533.3,1740.1 1565.16,1740.1 1567.53,1742.47 U21.93@1591.66,1742.47
XDSET_1_DP: J5.3 U9.5 U21.94 | length 3571
  Top Layer w7.5: U9.5@3820.35,263.22 3822.37,261.19 3830.06,261.19 3832.13,259.12 3868.13,259.12 v2(3877.28,268.28) 3886.26,259.3 3898.42,259.3 3901.34,262.22 3926.11,262.22 J5.3@3930.23,266.35
  L3_SIG1 w5: v2(1523.13,1720.81) 1524.22,1720.81 1532.56,1729.15 1554,1729.15 1716.56,1566.59 1716.56,1410.99 2637.31,490.24 2726.97,490.24 2892.87,324.35 2892.87,204.38 3018.14,79.1 3773.27,79.1 3916.7,222.53 3916.7,250.53 3905.68,261.55 3886.82,261.55 3880.09,268.28 v2(3877.28,268.28)
  Bottom Layer w6: v2(1523.13,1720.81) 1524.36,1720.81 1532.65,1729.1 1565.16,1729.1 1567.53,1726.72 U21.94@1591.66,1726.72
XDSET_1_ID: J5.4 R170.2 U9.2 | length 3642.1
  Top Layer w10.8: v2(3768.28,262.5) 3768.64,262.86 3796.37,262.86 U9.2@3796.72,263.22 ; v2(3884.64,298.44) 3884.64,297.4 3890.1,291.94 J5.4@3930.23,291.94
  L6_SIG2 w6: v2(1866.03,1667.13) 1939.51,1740.6 2178.4,1740.6 2225.83,1693.17 2669.17,1693.17 2749.86,1773.86 3168.44,1773.86 3224.68,1717.62 3270.87,1717.62 3453.23,1535.26 3453.23,1194.23 3410,1151 3410,900.09 3449.09,861 3463,861 3511.7,812.3 3511.7,514.97 3646.96,379.71 3646.96,337.61 3722.07,262.5 v2(3768.28,262.5) 3789.59,262.5 3844.81,317.72 3865.36,317.72 v2(3884.64,298.44)
  Bottom Layer w8.7: R170.2@1717.62,1701.9 1746.76,1701.9 1759.57,1714.7 1818.46,1714.7 v2(1866.03,1667.13)
XDSET_1_VBUS: R1.1 R169.2 R236.2 U9.6 | length 4492.4
  Top Layer w10.8: U9.6@3820.35,282.9 3820.35,306.3 3841.45,327.4 3841.45,368.31 v2(3827.9,381.86)
  L6_SIG2 w6: v2(871.01,1776.85) 1216.55,1776.85 1247.95,1745.46 1377.31,1745.46 1455.95,1666.81 1748.33,1666.81 v2(1773.57,1692.06) 1846.99,1765.47 2220.95,1765.47 2255.42,1731 2455,1731 2473.67,1712.33 2662.74,1712.33 2746.27,1795.86 3214.75,1795.86 3470.23,1540.37 3470.23,1177.37 3453.9,1161.03 3453.9,893.34 3527.61,819.64 3527.61,620.48 3616.09,532 3677.76,532 v2(3827.9,381.86)
  Bottom Layer w8.7: v2(871.01,1776.85) 871.39,1776.85 883.42,1764.81 R236.2@883.42,1752.47 ; R169.2@1674.64,1618.9 1679.57,1613.97 1715.6,1613.97 1773.47,1671.84 v2@1773.47,1691.95
XI_FTDI: C148.1 U27.2 Y3.1 | length 270.5
  Bottom Layer w8.7: Y3.1@1286.58,495.1 1254.02,495.1 1243.48,505.64 1243.48,581.74 1251.36,589.61 C148.1@1251.36,604 1247.21,608.15 1247.21,666.53 1261.78,681.1 U27.2@1298.34,681.1
XO_FTDI: C147.1 U27.3 Y3.3 | length 207.5
  Bottom Layer w8.7: Y3.3@1199.96,558.09 C147.1@1199.96,603.75 ; C147.1@1200.21,604 1200.05,604.16 1200.05,643.98 1256.86,700.79 U27.3@1298.34,700.79
XTALM: C33.2 U1.D4 Y1.1 | length 161.6
  Top Layer w4: v2(2398.27,2881.2) U1.D4@2408.12,2891.04
  Bottom Layer w8.7: v2(2398.27,2881.2) 2419.49,2902.41 C33.2@2450.78,2902.41 2470.37,2921.99 2489.39,2921.99 2501,2933.61 2503.25,2935.86 2503.25,2937.86 2514.61,2949.22 Y1.1@2516.61,2949.22
XTALP: C32.2 U1.F4 Y1.3 | length 186.5
  Top Layer w4: v2(2367.77,2876) 2368.75,2876.97 U1.F4@2368.75,2891.04 ; v2@2368.76,2875.02 v2@2368.76,2876
  Bottom Layer w8.7: v2@2368.77,2876 2368.77,2921.73 2412.51,2965.47 2412.51,2969.41 2435.68,2992.57 Y1.3@2461.5,2992.57
pads on no net: Designator6_2. Designator6_3. Designator6_4. Designator6_5. Designator6_6. Designator6_7. Designator6_8. Designator6_9. FID1.1 FID2.1 FID3.1 FID4.1 FID5.1 FID6.1 FID11.1 FID11_1.1 FID11_2.1 FID11_3.1 FID15.1 FID15_1.1 FID15_2.1 FID15_3.1 J6.14 J6.15 J6.16 J6.17 J6.19 J6.20 J6.21 J6.22 J6.23 J6.25 J6.27 J6.29 J6.31 J6.32 J6.33 J6.34 J6.35 J6.37 J6.38 J6.39 J6.40 J6.41 J6.43 J6.45 J6.47 J6.49 J6.MH1 J6.MH2 J7.ALIGN J11.3 J11.6 J11.8 J11.10 J11.11 J11.12 J11.16 J12.3 J12.4 J12.5 J12.7 J12.8 J12.11 J12.15 J12.18 J12.20 J14.2 LBL1.0 S7.MH1 S7.MH2 S8.MH1 S8.MH2 U10.7@3592.35,1118.68 U10.7@3627.78,1118.68 U11.1 U11.2 U13.2 U13.5 U13.7@3182.65,428.03 U13.7@3182.65,463.46 U20.4 U21.2 U21.3 U21.4 U21.5 U21.6 U21.11 U21.12 U21.13 U21.14 U21.15 U21.18 U21.19 U21.20 U21.21 U21.22 U21.23 U21.27 U21.29 U21.30 U21.31 U21.32 U21.41 U21.44 U21.45 U21.46 U21.49 U21.50 U21.53 U21.54 U21.56 U21.57 U21.65 U21.67 U21.71 U21.72 U21.73 U21.74 U21.75 U21.76 U21.77 U21.78 U21.81 U21.82 U21.83 U21.84 U21.85 U21.86 U21.91 U21.92 U21.97 U21.98 U21.99 U21.100 U21.102 U21.103 U21.104 U21.105 U21.106 U21.107 U21.108 U21.109 U21.110 U21.116 U21.117 U21.118 U21.119 U21.120 U21.121 U21.123 U21.124 U21.125 U21.126 U21.127 U21.128 U22.3 U23.3 U23.8 U26.6 U26.7 U27.21 U27.22 U27.23 U27.24 U27.29 U27.30 U27.33 U27.40 U27.41 U27.43 U27.44 U27.46 U27.53 U27.57 U27.58 U27.60 U28.12 U28.16 U28.22

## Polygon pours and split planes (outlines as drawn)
no net on Bottom Solder "NONET_L-01_P-001" (solid): 2238.97,2807.89 cw(c2238.97,2799.42) 2247.44,2799.42 2247.44,2663.09 cw(c2241.64,2663.09) 2241.64,2657.29 2161.09,2657.29 cw(c2161.09,2663.44) 2154.95,2663.44 2154.95,2801.8 cw(c2161.04,2801.8) 2161.04,2807.89
GND on L4_PWR1 "NONET_L08_P-001" (solid, remove dead copper, pour order 264): 2174.49,0 2174.49,381.95 2534.49,381.95 2534.49,0 4094.49,0 4094.49,3724.79 0,3724.79 0,0
VCC_3V3 on L4_PWR1 "VCC_3V3_L04_P251" (solid, remove dead copper, pour order 251): 68 vertices, not listed, extent 71,65 3843.02,3428.37
PMIC_OUT_3V3 on L4_PWR1 "NONET_L08_P-001" (solid, remove dead copper, pour order 167): 19 vertices, not listed, extent 520.78,1124.17 2429.6,2232.52
5V_IN_USB on L4_PWR1 "NONET_L08_P-001" (solid, remove dead copper, pour order 241): 3339.4,1391.03 ccw(c3339.4,1341.03) 3289.4,1341.03 3289.4,947.89 3290,926.78 cw(c3190,926.78) 3190,826.78 3114.95,826.78 ccw(c3114.95,726.78) 3014.95,726.78 3014.95,496.63 ccw(c3114.95,496.63) 3114.95,396.63 3723.56,396.63 ccw(c3723.56,474.07) 3801,474.07 3801,1357.85 ccw(c3767.82,1357.85) 3767.81,1391.03 3674.71,1391.03
RADAR_1V8 on L4_PWR1 "RADAR_1V8_L04_P236" (solid, remove dead copper, pour order 236): 42 vertices, not listed, extent 1825.39,2100.35 2582.93,3015.33
VCC_XDS_3V3 on L4_PWR1 "VCC_XDS_3V3_L04_P247" (solid, remove dead copper, pour order 247): 17 vertices, not listed, extent 855,1528 1695.33,2490.59
RADAR_1V2 on L4_PWR1 "RADAR_1V2_L04_P239" (solid, remove dead copper, pour order 239): 22 vertices, not listed, extent 2057.79,2622.17 2353.34,2802.79
FTDI_3V3 on L4_PWR1 "FTDI_3V3_L04_P249" (solid, remove dead copper, pour order 249): 19 vertices, not listed, extent 1043,209 2064.55,1206
GND on Top Layer "NONET_L08_P-001" (solid, remove dead copper, pour order 274): 2174.49,0 2174.49,381.95 2534.49,381.95 2534.49,0 4094.49,0 4094.49,3724.79 0,3724.79 0,0
VCC_12V on Top Layer "NONET_L08_P-001" (solid, remove dead copper, pour order 52): 19 vertices, not listed, extent 2451.29,761.63 3143.29,1148.27
REG_RF_1V2 on Top Layer "NONET_L08_P-001" (solid, remove dead copper, pour order 73): 17 vertices, not listed, extent 2865.66,1225.48 3195.81,1553.92
MCU_5V on Top Layer "NONET_L-01_P-001" (solid, remove dead copper, pour order 273): 763.77,1380.6 781.2,1398.03 790.43,1398.03 799.84,1398.03 828.66,1398.03 828.66,1408.02 828.66,1431.53 828.66,1447.94 778.4,1447.94 754.8,1447.94 739.03,1447.94 715.56,1424.47 715.56,1324.81 763.77,1324.81
VSYS_IN on Top Layer "NONET_L-01_P-001" (solid, remove dead copper, pour order 265): 767.25,1202.86 ccw(c767.25,1209.98) 774.37,1209.98 774.37,1293.96 ccw(c767.14,1293.96) 767.14,1301.19 702.21,1301.19 ccw(c702.21,1295.13) 696.14,1295.13 696.14,1208.7 ccw(c701.98,1208.7) 701.98,1202.86
PMIC_OUT_3V3 on Top Layer "NONET_L08_P-001" (solid, remove dead copper, pour order 119): 2364.34,1453.04 2364.34,1478.16 2366.94,1480.76 2366.94,1493.99 2366.89,1494.04 2304.83,1494.04 2291.06,1480.27 2291.06,1458.17 2280.35,1447.47 2262.16,1447.47 2260.12,1445.43 2259.77,1436.54 2261.83,1434.48 2345.78,1434.48
PMIC_OUT_3V3 on Top Layer "NONET_L08_P-001" (solid, remove dead copper, pour order 121): 2364.34,1348.49 2364.34,1323.37 2366.94,1320.78 2366.94,1307.54 2366.89,1307.5 2304.83,1307.5 2291.06,1321.26 2291.06,1343.36 2280.35,1354.07 2262.16,1354.07 2260.12,1356.11 2259.77,1365 2261.83,1367.06 2345.78,1367.06
VSYS_IN on Top Layer "NONET_L08_P-001" (solid, remove dead copper, pour order 61): 18 vertices, not listed, extent 2118,1046.3 2248.32,1349.16
NetD1_2 on Top Layer "NONET_L08_P-001" (solid, remove dead copper, pour order 201): 3713.15,295.91 3743.76,265.31 3743.76,135.31 3734.43,125.99 3633.86,125.99 cw(c3633.86,156.28) 3603.56,156.28 3603.56,272.41 cw(c3627.06,272.41) 3627.06,295.91
5V_IN_USB on Top Layer "Top Layer-5V_IN_USB" (solid, remove dead copper, pour order 190): 46 vertices, not listed, extent 3155.14,317.72 3808.14,939.76
12V_DC_JACK on Top Layer "NONET_L08_P-001" (solid, remove dead copper, pour order 223): 21 vertices, not listed, extent 3290.51,665.61 3777,1089.73
PMIC_OUT_1V2 on Top Layer "NONET_L08_P-001" (solid, remove dead copper, pour order 71): 2387.76,1331.34 2838.29,1331.34 2853.62,1316.01 2853.62,1207.8 2838.58,1192.76 2395.95,1192.76 2375,1213.7 2375,1317.78
PMIC_VDD_1V8 on Top Layer "NONET_L08_P-001" (solid, remove dead copper, pour order 67): 2148.54,1425.37 2109.81,1425.37 2101.1,1434.08 2101.1,1447.98 2094.8,1454.28 2059.04,1454.28 2056.88,1452.11 2056.88,1415.66 2104.63,1415.66 2150.17,1415.66 2151.09,1416.58 2151.09,1424.32
PMIC_OUT_3V3 on Top Layer "NONET_L08_P-001" (solid, remove dead copper, pour order 64): 1774.88,1333.17 1745.85,1362.2 1648,1362.2 1643.84,1358.04 1643.84,1208.59 1649.57,1202.86 1991.93,1202.86 2017.82,1176.97 2037.33,1176.97 2058.42,1198.06 2058.42,1266.31 2044.61,1280.12 2044.61,1327.27 2038.71,1333.17
NetD12_2 on Top Layer "NONET_L08_P-001" (solid, remove dead copper, pour order 83): 3717.41,1565.95 3717.41,1494.45 3723.39,1488.47 3744.84,1488.47 3750.8,1482.51 3750.8,1433.17 3745.79,1428.16 3745.08,1428.88 3643.06,1428.88 3636.55,1435.39 3636.55,1553.63 3648.87,1565.95
PMIC_OUT_3V3 on Top Layer "NONET_L08_P-001" (solid, remove dead copper, pour order 181): 2203.93,1557.73 2200.9,1560.76 2181.01,1560.76 2169.91,1571.86 2155.07,1571.86 2150.45,1567.24 2150.45,1539.28 2156.36,1533.37 2201.19,1533.37 2203.93,1536.11
VSYS_IN on Top Layer "NONET_L08_P-001" (solid, remove dead copper, pour order 42): 3156.62,750.28 3218.16,750.28 3232.04,736.4 3232.04,711.51 3227.18,706.65 3196.09,706.65 3194.09,708.65 3194.09,726.09 3187.16,733.02 3156.62,733.02 3154.41,735.23 3154.43,735.25 3154.43,748.76
PMIC_B2_SW on Top Layer "NONET_L08_P-001" (solid, remove dead copper, pour order 43): 2376.11,1468.87 2373.38,1466.15 2373.18,1452.58 2350.3,1429.69 2259.54,1429.69 2255.76,1425.92 2255.76,1416.84 2258.32,1414.28 2370.56,1414.28 2419.22,1414.28 2448.72,1443.78 2448.72,1464.75 2444.59,1468.87
PMIC_B3_SW on Top Layer "NONET_L08_P-001" (solid, remove dead copper, pour order 44): 2376.8,1345.12 2437.8,1345.12 2438.9,1346.22 2438.9,1367.57 2420.12,1386.35 2255.76,1386.35 2255.76,1374.1 2347.81,1374.1
VCC_XDS_3V3 on Top Layer "NONET_L08_P-001" (solid, remove dead copper, pour order 50): 3151.81,477.46 3150.16,479.11 3095.64,479.11 3087.97,486.78 3087.97,496.13 3083,501.1 3066.73,501.1 3061.63,496 3061.63,460.13 3063.72,458.04 3147.38,458.04 3153.45,464.11 3153.45,475.21 3153.58,475.34
VSYS_IN on Top Layer "NONET_L08_P-001" (solid, remove dead copper, pour order 53): 3144.48,752.64 3145.07,752.05 3145.07,735.37 3145.15,735.29 3143.6,733.74 3105.81,733.74 3101.43,729.37 3101.43,720.17 3095.54,714.27 3070.94,714.27 3063.98,721.23 3063.98,745.09 3071.53,752.64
